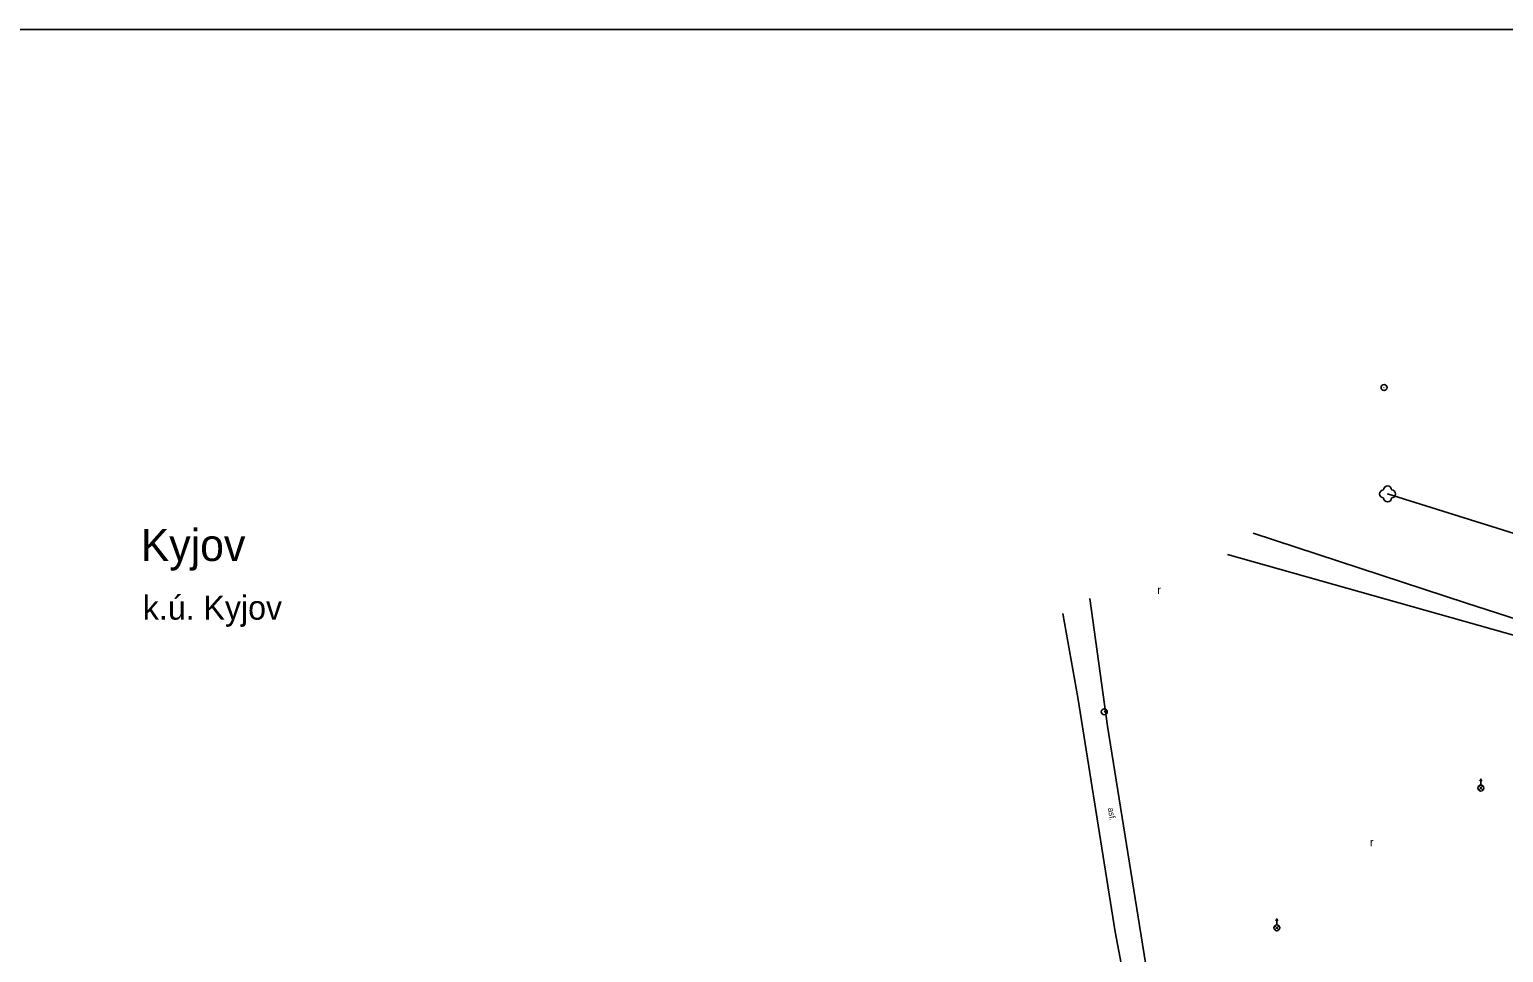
# Model space of a CAD drawing. Extents: x -582188 to -561562, y -1187250 to -1183500.
# Drawn here: x -562415.3 to -562231.1, y -1186115.3 to -1186000 of the extents above; entities that cross this region are included whole.
import ezdxf

# ---------------------------------------------------------------- set-up
doc = ezdxf.new("R2010")
doc.units = 0
for name, color, linetype in [('MAP_ZN_BP', 7, 'Continuous'), ('NÁZEV_K_Ú', 7, 'Continuous'), ('NÁZVY_SÍDEL_JEDNOTKY', 7, 'Continuous'), ('POMOC_POPIS', 7, 'Continuous'), ('ROZHRANÍ_PLOCH', 7, 'Continuous'), ('RÁMY_ML', 7, 'Continuous'), ('ZELEŇ', 7, 'Continuous'), ('ZN_BP', 7, 'Continuous'), ('ZN_KULTUR', 7, 'Continuous')]:
    doc.layers.add(name, color=color, linetype=linetype)

msp = doc.modelspace()

# ---------------------------------------------------------------- linework, layer by layer
at = {"layer": 'MAP_ZN_BP'}
for centre, radius in [((-562246.05, -1186044.711), 0.375), ((-562246.05, -1186044.711), 0.0005), ((-562281, -1186085.211), 0.375), ((-562281, -1186085.211), 0.0005)]:
    msp.add_circle(centre, radius, dxfattribs=at)
at = {"layer": 'ROZHRANÍ_PLOCH'}
for p, q in [((-562280.6, -1186087.01), (-562282.82, -1186071.06)), ((-562286.2, -1186072.93), (-562284.32, -1186083.44)), ((-562284.32, -1186083.44), (-562279.63, -1186112.7))]:
    msp.add_line(p, q, dxfattribs=at)
for points in [[(-562262.4, -1186062.89), (-562235.74, -1186071.63), (-562225.56, -1186074.94), (-562206.22, -1186077.46), (-562095.95, -1186111.38)], [(-562265.6, -1186065.58), (-562226.07, -1186076.72), (-562224.4, -1186077.78), (-562206.63, -1186079.4), (-562195.25, -1186082.43), (-562093.12, -1186114.26)], [(-562275.86, -1186116.57), (-562280.6, -1186087.01)], [(-562271.45, -1186148.44), (-562274.65, -1186136.81), (-562277.28, -1186125.3), (-562278.91, -1186116.63), (-562279.63, -1186112.7)]]:
    msp.add_lwpolyline(points, dxfattribs=at)
at = {"layer": 'RÁMY_ML'}
msp.add_lwpolyline([(-561875, -1186000), (-562500, -1186000)], dxfattribs=at)
at = {"layer": 'ZELEŇ'}
msp.add_lwpolyline([(-562245.61, -1186058), (-562199.6, -1186072.39), (-562190.54, -1186074.94)], dxfattribs=at)
msp.add_circle((-562245.61, -1186058), 0.0005, dxfattribs=at)
for centre, start, end in [((-562245.61, -1186057.5), 0, 179.99999), ((-562246.11, -1186058), 89.99999, 269.99999), ((-562245.61, -1186058.5), 179.99999, 359.99999), ((-562245.11, -1186058), 270, 89.99999)]:
    msp.add_arc(centre, 0.5, start, end, dxfattribs=at)
at = {"layer": 'ZN_BP'}
for p, q in [((-562233.96, -1186094.355), (-562233.96, -1186093.605)), ((-562234.225, -1186094.994), (-562233.696, -1186094.466)), ((-562233.696, -1186094.998), (-562234.225, -1186094.466)), ((-562259.715, -1186112.454), (-562259.186, -1186111.926)), ((-562259.186, -1186112.458), (-562259.715, -1186111.926)), ((-562259.45, -1186111.815), (-562259.45, -1186111.065))]:
    msp.add_line(p, q, dxfattribs=at)
for points in [[(-562234.085, -1186093.855), (-562233.96, -1186093.605), (-562233.835, -1186093.855)], [(-562259.575, -1186111.315), (-562259.45, -1186111.065), (-562259.325, -1186111.315)]]:
    msp.add_lwpolyline(points, dxfattribs=at)
for centre in [(-562233.96, -1186094.73), (-562259.45, -1186112.19)]:
    msp.add_circle(centre, 0.375, dxfattribs=at)

# ---------------------------------------------------------------- texts
at = {"layer": 'NÁZEV_K_Ú'}
msp.add_text('k.ú. Kyjov', height=3, dxfattribs=at).set_placement((-562401.12, -1186073.7))
at = {"layer": 'NÁZVY_SÍDEL_JEDNOTKY'}
msp.add_text('Kyjov', height=4, dxfattribs=at).set_placement((-562401.39, -1186066.38))
at = {"layer": 'POMOC_POPIS'}
msp.add_text('asf.', height=0.75, rotation=279.14, dxfattribs=at).set_placement((-562280.56, -1186097.24))
at = {"layer": 'ZN_KULTUR'}
for p in [(-562274.378, -1186070.492), (-562247.818, -1186102.002)]:
    msp.add_text('r', height=1, dxfattribs=at).set_placement(p)

doc.saveas('drawing.dxf')
